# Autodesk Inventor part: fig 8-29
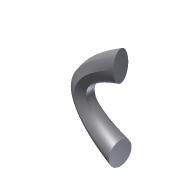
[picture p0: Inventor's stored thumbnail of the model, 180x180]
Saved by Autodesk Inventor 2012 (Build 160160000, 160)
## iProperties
Created: 2008-06
Part Number: fig 8-29
Document SubType Name: Modeling
Designer: CADCIM
Density: 1 g/cm^3
Material: Default
Author: CADCIM
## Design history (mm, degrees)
sketch "Sketch1"
  geometry: L1 (-0.077, 5.773)-(4.961, 2.953); L2 (4.961, 2.953)-(5.038, -2.82); L3 (5.038, -2.82)-(0.077, -5.773); L4 (0.077, -5.773)-(-4.961, -2.953); L5 (-4.961, -2.953)-(-5.038, 2.82); L6 (-5.038, 2.82)-(-0.077, 5.773); 1 further point
  constraints: 12 end point, 13 other
  dimensions: "d0" = 10 distance between parallel lines of L2 L5
workplane "Work Plane1"
sketch "Sketch2"
  geometry: C1 r 7.5 at (-0.159, -25); 1 further point
  constraints: 1 centre point
  dimensions: "d2" = 15 diameter of C1; "d3" = 25 vertical distance of C1.centre point (0, 0)
sketch "Sketch3" dims "d4" = 10, "d5" = 5
  geometry: 2 further points; 1 other entity
  constraints: 2 other
  dimensions: "d6" = 25 vertical distance of point (0.175, 25) point (0, 0)
loft "Loft1" sketch "Sketch2", "Sketch3" dims "d7" = 0, "d8" = 90 deg, "d9" = 0, "d10" = 90 deg, "d11" = 0, "d12" = 90 deg
body "Solid1"
other parameters: "d1" = 25
